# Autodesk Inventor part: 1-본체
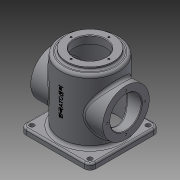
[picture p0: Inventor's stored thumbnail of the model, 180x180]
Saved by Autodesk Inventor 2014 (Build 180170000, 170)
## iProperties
Created: 2015-10
Part Number: 1-본체
Material: 일반
Document SubType Name: Modeling
Designer: Administrator
Density: 1 g/cm^3
Appearance: 기본값
Author: Administrator
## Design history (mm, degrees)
sketch "스케치1"
  geometry: L1 (50, -50)-(0, -50); L2 (0, -50)-(0, 60); L3 (0, 60)-(50, 60); L4 (50, 60)-(50, -50); L5 (0, 60)-(40, 60); L6 (40, 60)-(40, 65); L7 (40, 65)-(0, 65); L8 (0, 65)-(0, 60); L9 (0, -50)-(45, -50); L10 (45, -50)-(45, 52); L11 (45, 52)-(0, 52); L12 (0, 52)-(0, -50); 1 further point
  constraints: 24 end point, 6 parallel, 3 horizontal, 3 perpendicular, 1 point on line
  dimensions: "d0" = 110 distance of L3.end L1.start; "d1" = 5 distance of L5.end L6.end; "d2" = 80 diameter of L6 L2; "d3" = 100 diameter of L4 L2; "d4" = 50 distance from line of point (0, 0) L1; "d5" = 102 distance of L9.end L10.end; "d6" = 90 diameter of L10 L2
revolve "회전1" sketch "스케치1" stored, may be unused: angle "d7" = 90 deg
sketch "스케치2"
  geometry: L1 (-60, -60)-(60, -60); L2 (60, -60)-(60, 60); L3 (60, 60)-(-60, 60); L4 (-60, 60)-(-60, -60); C1 r 45 at (0, 0) reference; 3 further points
  constraints: 8 end point, 2 midpoint, 2 parallel, 1 horizontal, 1 horizontal alignment, 1 perpendicular, 1 vertical alignment
  dimensions: "d8" = 120 distance between parallel lines of L3 L1; "d9" = 120 distance between parallel lines of L2 L4 (= d8)
extrude "돌출1" join sketch "스케치2" distance "d10" = 10; taper "d11" = 0 deg
node "작업 평면1"
sketch "스케치3"
  geometry: L1 (60, -60)-(-60, -60) reference; C1 r 40 at (0, 0); 1 further point
  constraints: 1 centre point, 1 coincident
  dimensions: "d13" = 60 distance from line of L1 C1.centre; "d14" = 80 diameter of C1
extrude "돌출2" join sketch "스케치3" stored distance "d15" = 0; taper "d16" = 0 deg
hole "구멍1" diameter "d19" = 54; stored, may be unused: countersink angle "d23" = 90 deg, drill point angle "d25" = 118 deg; dims "d17" = 10, "d18" = 10, "d20" = 6, "d21" = 4, "d22" = 2, "d24" = 8
hole "구멍2" diameter "d28" = 54; stored, may be unused: countersink angle "d32" = 90 deg, drill point angle "d34" = 118 deg; dims "d26" = 10, "d27" = 10, "d29" = 6, "d30" = 4, "d31" = 2, "d33" = 8
sketch "스케치4"
  geometry: L1 (0, 0)-(-32.5, 0)
  constraints: 2 end point, 1 horizontal
  dimensions: "d35" = 32.5 distance of L1.start L1.end
hole "구멍3" sketch "스케치4" at (-32.5, 0) diameter "d36" = 3.242; stored, may be unused: countersink angle "d40" = 90 deg, drill point angle "d42" = 118 deg; dims "d37" = 8, "d38" = 4, "d39" = 2, "d41" = 10
sketch "스케치5"
  geometry: L1 (0, 0)-(32.5, 0)
  constraints: 2 end point, 1 horizontal
  dimensions: "d46" = 32.5 distance of L1.start L1.end
hole "구멍4" sketch "스케치5" at (32.5, 0) diameter "d47" = 3.242; stored, may be unused: countersink angle "d51" = 90 deg, drill point angle "d53" = 118 deg; dims "d48" = 8, "d49" = 4, "d50" = 2, "d52" = 10
sketch "스케치6"
  geometry: L1 (0, 0)-(32.5, 0)
  constraints: 2 end point, 1 horizontal
  dimensions: "d57" = 32.5 distance of L1.start L1.end
hole "구멍5" sketch "스케치6" at (32.5, 0) diameter "d58" = 3.242; stored, may be unused: countersink angle "d62" = 90 deg, drill point angle "d64" = 118 deg; dims "d59" = 8, "d60" = 4, "d61" = 2, "d63" = 10
sketch "스케치7"
  geometry: L1 (-50, -50)-(50, -50); L2 (50, -50)-(50, 50); L3 (50, 50)-(-50, 50); L4 (-50, 50)-(-50, -50); 3 further points
  constraints: 8 end point, 2 midpoint, 2 parallel, 1 horizontal, 1 horizontal alignment, 1 perpendicular, 1 vertical alignment
  dimensions: "d68" = 100 distance between parallel lines of L2 L4; "d69" = 100 distance between parallel lines of L3 L1 (= d68)
hole "구멍6" sketch "스케치7" at (0, 0), (-50, -50), (50, 50), (50, -50), (-50, 50) diameter "d70" = 8; stored, may be unused: countersink angle "d74" = 90 deg, drill point angle "d76" = 118 deg; dims "d71" = 8, "d72" = 4, "d73" = 2, "d75" = 10
chamfer "모따기1" distance "d77" = 3; stored, may be unused: second distance "d78" = 2, angle "d79" = 45 deg
fillet "모깎기1" dims "d80" = 5
chamfer "모따기2" distance "d81" = 1; stored, may be unused: second distance "d82" = 2, angle "d83" = 45 deg
fillet "모깎기2" dims "d84" = 3
fillet "모깎기3" dims "d85" = 10
fillet "모깎기4" dims "d86" = 3
node "작업 평면3"
  node "작업 평면2"
sketch "스케치8"
  geometry: L1 (-4.139, 2.368)-(-4.139, 7.632); L2 (-4.139, 7.632)-(4.139, 7.632); L3 (4.139, 7.632)-(4.139, 2.368); L4 (4.139, 2.368)-(-4.139, 2.368); L5 (50, -65)-(-50, -65) reference; 3 further points
  constraints: 2 midpoint, 1 vertical, 1 vertical alignment, 2 other
  dimensions: "d88" = 70 distance from line of point (4.139, 5) L5
feature "엠보싱1" sketch "스케치8" dims "d0" = 110, "d1" = 5, "d2" = 80, "d3" = 100, "d4" = 50, "d5" = 102, "d6" = 90, "d89" = 0.5, "d90" = 0
node "솔리드1"
mirror "대칭1"
pattern_circular "원형 패턴1" dims angle "d44" = 360 deg
pattern_circular "원형 패턴2" dims angle "d55" = 360 deg
pattern_circular "원형 패턴3" dims angle "d66" = 360 deg
other parameters: "d12" = 62, "d87" = 0.5
